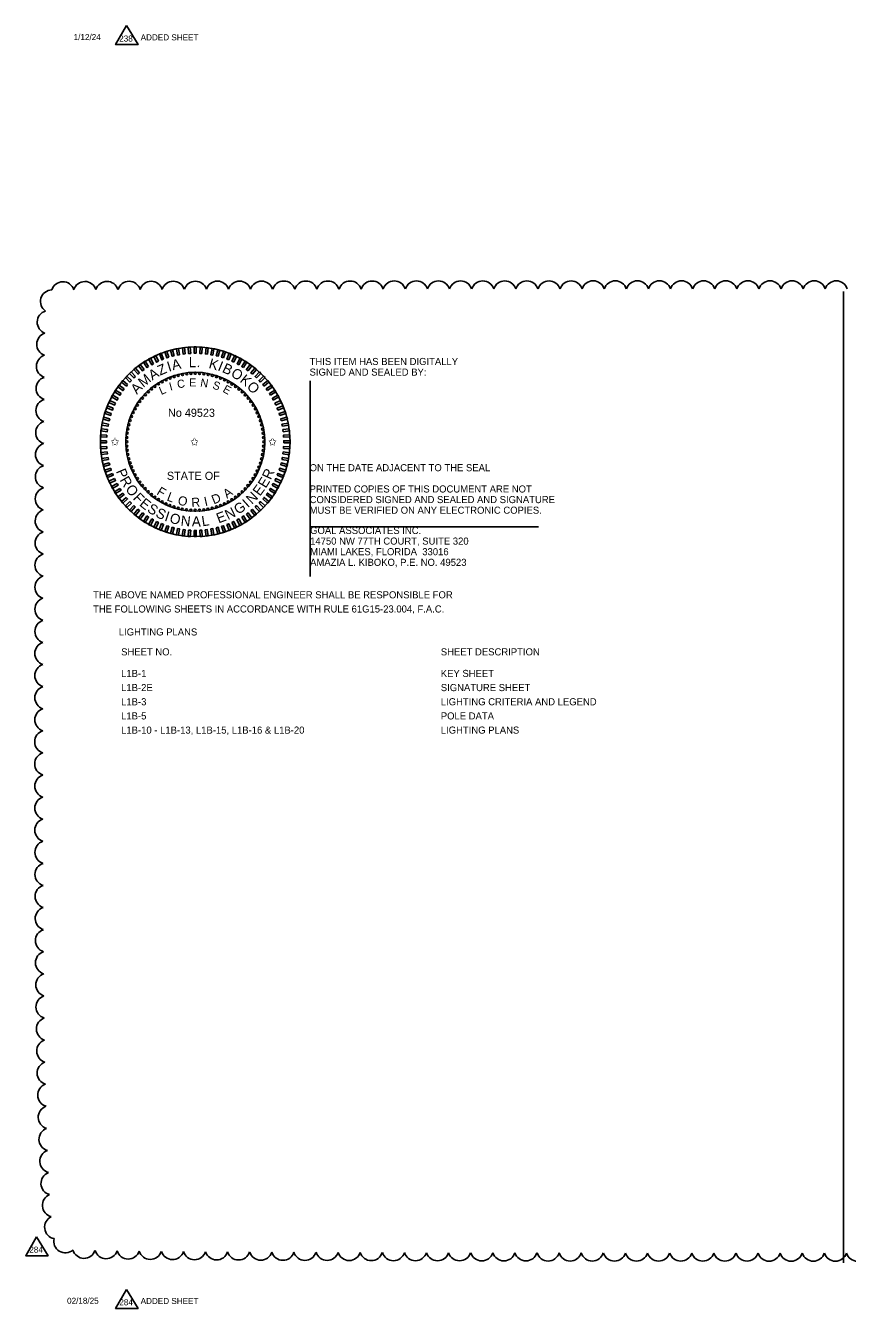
# Model space of a CAD drawing. Extents: x -811.2 to -795, y -2307.6 to -2235.1.
# Drawn here: x -811.17 to -803.05, y -2307.46 to -2294.79 of the extents above; entities that cross this region are included whole.
import ezdxf

# ---------------------------------------------------------------- set-up
doc = ezdxf.new("R2010")
doc.units = 0
for name, color, linetype in [('AdhocPoint_dp', 7, 'Continuous'), ('Cloud_dp', 7, 'Continuous'), ('Logo_dp', 7, 'Continuous'), ('TeleMisc', 7, 'Continuous'), ('TextDetails', 7, 'Continuous'), ('TextMinor', 7, 'Continuous'), ('TextMisc', 7, 'Continuous'), ('TextNotes', 7, 'Continuous')]:
    doc.layers.add(name, color=color, linetype=linetype)

msp = doc.modelspace()

# ---------------------------------------------------------------- linework, layer by layer
at = {"layer": 'AdhocPoint_dp'}
for p, q in [((-808.355, -2298.295), (-808.355, -2300.229)), ((-808.355, -2299.739), (-806.098, -2299.739))]:
    msp.add_line(p, q, dxfattribs=at)
at = {"layer": 'Cloud_dp'}
for points in [[(-810.168, -2294.785), (-810.276, -2294.973), (-810.055, -2294.973)], [(-811.057, -2306.754), (-811.165, -2306.942), (-810.944, -2306.942)], [(-810.168, -2307.274), (-810.276, -2307.462), (-810.055, -2307.462)]]:
    msp.add_lwpolyline(points, close=True, dxfattribs=at)
for centre, start, end in [((-810.798, -2297.43), 18.0566, 163.0566), ((-810.58, -2297.428), 17.7998, 162.7998), ((-810.362, -2297.427), 17.7187, 162.7187), ((-810.143, -2297.426), 17.6743, 162.6743), ((-809.925, -2297.426), 17.6451, 162.6451), ((-809.707, -2297.425), 17.624, 162.624), ((-809.488, -2297.425), 17.6079, 162.6079), ((-809.27, -2297.424), 17.5951, 162.5951), ((-809.052, -2297.424), 17.5845, 162.5845), ((-808.834, -2297.424), 17.5756, 162.5756), ((-808.615, -2297.423), 17.568, 162.568), ((-808.397, -2297.423), 17.5614, 162.5614), ((-808.179, -2297.423), 17.5556, 162.5556), ((-807.96, -2297.423), 17.5505, 162.5505), ((-807.742, -2297.423), 17.5459, 162.5459), ((-807.524, -2297.422), 17.5417, 162.5417), ((-807.305, -2297.422), 17.5379, 162.5379), ((-807.087, -2297.422), 17.5344, 162.5344), ((-806.869, -2297.422), 17.5313, 162.5313), ((-806.65, -2297.422), 17.5283, 162.5283), ((-806.432, -2297.422), 17.5256, 162.5256), ((-806.214, -2297.422), 17.5231, 162.5231), ((-805.995, -2297.422), 17.5207, 162.5207), ((-805.777, -2297.422), 17.5185, 162.5185), ((-805.559, -2297.421), 17.5164, 162.5164), ((-805.34, -2297.421), 17.5145, 162.5145), ((-805.122, -2297.421), 17.5126, 162.5126), ((-804.904, -2297.421), 17.5109, 162.5109), ((-804.685, -2297.421), 17.5092, 162.5092), ((-804.467, -2297.421), 17.5077, 162.5077), ((-804.249, -2297.421), 17.5062, 162.5062), ((-804.03, -2297.421), 17.5048, 162.5048), ((-803.812, -2297.421), 17.5034, 162.5034), ((-803.594, -2297.421), 17.5021, 162.5021), ((-803.375, -2297.421), 17.5009, 162.5009), ((-803.157, -2297.421), 17.5, 162.5), ((-810.905, -2297.511), 91.4771, 236.4771), ((-810.937, -2297.716), 105.908, 250.908), ((-810.942, -2297.934), 106.4168, 251.4168), ((-810.945, -2298.152), 106.6762, 251.6762), ((-810.948, -2298.37), 106.841, 251.841), ((-810.95, -2298.589), 106.9576, 251.9576), ((-810.952, -2298.807), 107.0457, 252.0457), ((-810.954, -2299.025), 107.1154, 252.1154), ((-810.955, -2299.243), 107.1722, 252.1722), ((-810.956, -2299.462), 107.2198, 252.2198), ((-810.957, -2299.68), 107.2603, 252.2603), ((-810.958, -2299.898), 107.2954, 252.2954), ((-810.959, -2300.117), 107.3262, 252.3262), ((-810.96, -2300.335), 107.3535, 252.3535), ((-810.96, -2300.553), 107.3779, 252.3779), ((-810.96, -2300.772), 107.3998, 252.3998), ((-810.961, -2300.99), 107.4198, 252.4198), ((-810.961, -2301.208), 107.438, 252.438), ((-810.961, -2301.427), 107.4547, 252.4547), ((-810.961, -2301.645), 107.4701, 252.4701), ((-810.962, -2301.863), 107.4843, 252.4843), ((-810.962, -2302.081), 107.499, 252.499), ((-810.961, -2302.3), 107.5356, 252.5356), ((-810.961, -2302.518), 107.5822, 252.5822), ((-810.961, -2302.736), 107.6325, 252.6325), ((-810.96, -2302.955), 107.6869, 252.6869), ((-810.959, -2303.173), 107.7461, 252.7461), ((-810.958, -2303.391), 107.8108, 252.8108), ((-810.957, -2303.61), 107.8818, 252.8818), ((-810.955, -2303.828), 107.9604, 252.9604), ((-810.954, -2304.046), 108.0479, 253.0479), ((-810.951, -2304.264), 108.1461, 253.1461), ((-810.949, -2304.483), 108.2576, 253.2576), ((-810.945, -2304.701), 108.3854, 253.3854), ((-810.942, -2304.919), 108.534, 253.534), ((-810.938, -2305.137), 108.7099, 253.7099), ((-810.932, -2305.355), 108.9225, 253.9225), ((-810.927, -2305.573), 109.1867, 254.1867), ((-810.92, -2305.791), 109.5275, 254.5275), ((-810.911, -2306.009), 109.9909, 254.9909), ((-810.9, -2306.227), 110.6749, 255.6749), ((-810.886, -2306.444), 111.8417, 256.8417), ((-810.864, -2306.66), 114.6718, 259.6718), ((-810.774, -2306.799), 166.2299, 311.2299), ((-810.588, -2306.854), 196.1072, 341.1072), ((-810.37, -2306.858), 196.5738, 341.5738), ((-810.152, -2306.861), 196.7877, 341.7877), ((-809.934, -2306.864), 196.9179, 341.9179), ((-809.715, -2306.866), 197.008, 342.008), ((-809.497, -2306.867), 197.075, 342.075), ((-809.279, -2306.869), 197.1274, 342.1274), ((-809.061, -2306.87), 197.1699, 342.1699), ((-808.842, -2306.872), 197.2052, 342.2052), ((-808.624, -2306.873), 197.2352, 342.2352), ((-808.406, -2306.874), 197.261, 342.261), ((-808.187, -2306.874), 197.2836, 342.2836), ((-807.969, -2306.875), 197.3036, 342.3036), ((-807.751, -2306.876), 197.3214, 342.3214), ((-807.532, -2306.877), 197.3374, 342.3374), ((-807.314, -2306.877), 197.3519, 342.3519), ((-807.096, -2306.878), 197.3651, 342.3651), ((-806.878, -2306.878), 197.3773, 342.3773), ((-806.659, -2306.879), 197.3884, 342.3884), ((-806.441, -2306.879), 197.3987, 342.3987), ((-806.223, -2306.879), 197.4083, 342.4083), ((-806.004, -2306.88), 197.4172, 342.4172), ((-805.786, -2306.88), 197.4256, 342.4256), ((-805.568, -2306.88), 197.4334, 342.4334), ((-805.349, -2306.881), 197.4407, 342.4407), ((-805.131, -2306.881), 197.4476, 342.4476), ((-804.913, -2306.881), 197.4542, 342.4542), ((-804.694, -2306.881), 197.4604, 342.4604), ((-804.476, -2306.881), 197.4662, 342.4662), ((-804.258, -2306.881), 197.4718, 342.4718), ((-804.039, -2306.881), 197.4771, 342.4771), ((-803.821, -2306.882), 197.4821, 342.4821), ((-803.603, -2306.882), 197.487, 342.487), ((-803.384, -2306.882), 197.4916, 342.4916), ((-803.166, -2306.882), 197.496, 342.496), ((-802.948, -2306.882), 197.5011, 342.5011)]:
    msp.add_arc(centre, 0.114, start, end, dxfattribs=at)
at = {"layer": 'TextDetails'}
for radius in [0.937, 0.687]:
    msp.add_circle((-809.49, -2298.898), radius, dxfattribs=at)
at = {"layer": 'TextMisc'}
for p, q in [((-809.5, -2299.835), (-809.5, -2299.773)), ((-809.49, -2299.835), (-809.49, -2299.773)), ((-809.48, -2299.835), (-809.48, -2299.773))]:
    msp.add_line(p, q, dxfattribs=at)
for points in [[(-809.698, -2298.048), (-809.717, -2298.053), (-809.733, -2297.993), (-809.713, -2297.988)], [(-809.644, -2298.037), (-809.664, -2298.041), (-809.676, -2297.979), (-809.656, -2297.976)], [(-809.59, -2298.029), (-809.61, -2298.031), (-809.617, -2297.97), (-809.597, -2297.967)], [(-809.535, -2298.024), (-809.555, -2298.026), (-809.559, -2297.963), (-809.539, -2297.962)], [(-809.48, -2298.023), (-809.5, -2298.023), (-809.5, -2297.961), (-809.48, -2297.961)], [(-809.425, -2298.026), (-809.445, -2298.024), (-809.441, -2297.962), (-809.421, -2297.963)], [(-809.37, -2298.031), (-809.39, -2298.029), (-809.383, -2297.967), (-809.363, -2297.97)], [(-809.316, -2298.041), (-809.336, -2298.037), (-809.324, -2297.976), (-809.305, -2297.979)], [(-809.263, -2298.053), (-809.282, -2298.048), (-809.267, -2297.988), (-809.247, -2297.993)], [(-809.95, -2298.154), (-809.967, -2298.165), (-810.001, -2298.112), (-809.984, -2298.101)], [(-809.903, -2298.127), (-809.92, -2298.136), (-809.95, -2298.082), (-809.933, -2298.072)], [(-809.853, -2298.102), (-809.872, -2298.111), (-809.898, -2298.054), (-809.88, -2298.046)], [(-809.803, -2298.081), (-809.821, -2298.088), (-809.844, -2298.03), (-809.826, -2298.023)], [(-809.751, -2298.063), (-809.77, -2298.069), (-809.789, -2298.01), (-809.77, -2298.004)], [(-809.21, -2298.069), (-809.229, -2298.063), (-809.21, -2298.004), (-809.191, -2298.01)], [(-809.159, -2298.088), (-809.177, -2298.081), (-809.154, -2298.023), (-809.136, -2298.03)], [(-809.108, -2298.111), (-809.127, -2298.102), (-809.1, -2298.046), (-809.082, -2298.054)], [(-809.06, -2298.136), (-809.077, -2298.127), (-809.047, -2298.072), (-809.03, -2298.082)], [(-809.013, -2298.165), (-809.03, -2298.154), (-808.996, -2298.101), (-808.979, -2298.112)], [(-810.121, -2298.292), (-810.135, -2298.307), (-810.18, -2298.264), (-810.166, -2298.249)], [(-810.081, -2298.253), (-810.096, -2298.267), (-810.139, -2298.222), (-810.124, -2298.208)], [(-810.04, -2298.218), (-810.055, -2298.23), (-810.095, -2298.182), (-810.08, -2298.169)], [(-809.996, -2298.184), (-810.012, -2298.196), (-810.049, -2298.146), (-810.033, -2298.134)], [(-808.968, -2298.196), (-808.984, -2298.184), (-808.947, -2298.134), (-808.931, -2298.146)], [(-808.925, -2298.231), (-808.94, -2298.218), (-808.9, -2298.17), (-808.885, -2298.182)], [(-808.884, -2298.267), (-808.899, -2298.254), (-808.856, -2298.208), (-808.841, -2298.222)], [(-808.846, -2298.307), (-808.859, -2298.292), (-808.814, -2298.249), (-808.8, -2298.264)], [(-810.192, -2298.376), (-810.204, -2298.392), (-810.254, -2298.355), (-810.242, -2298.339)], [(-810.158, -2298.333), (-810.17, -2298.348), (-810.219, -2298.308), (-810.206, -2298.293)], [(-808.81, -2298.348), (-808.823, -2298.333), (-808.774, -2298.293), (-808.762, -2298.309)], [(-808.777, -2298.392), (-808.788, -2298.376), (-808.738, -2298.339), (-808.726, -2298.355)], [(-810.277, -2298.516), (-810.286, -2298.535), (-810.342, -2298.508), (-810.334, -2298.49)], [(-810.252, -2298.468), (-810.261, -2298.485), (-810.316, -2298.455), (-810.306, -2298.438)], [(-810.223, -2298.421), (-810.234, -2298.438), (-810.287, -2298.404), (-810.276, -2298.387)], [(-808.746, -2298.438), (-808.757, -2298.421), (-808.704, -2298.387), (-808.693, -2298.404)], [(-808.719, -2298.486), (-808.728, -2298.468), (-808.674, -2298.438), (-808.664, -2298.455)], [(-808.694, -2298.535), (-808.703, -2298.517), (-808.646, -2298.49), (-808.638, -2298.508)], [(-810.319, -2298.618), (-810.325, -2298.637), (-810.384, -2298.618), (-810.378, -2298.599)], [(-810.3, -2298.567), (-810.307, -2298.585), (-810.365, -2298.562), (-810.358, -2298.544)], [(-808.673, -2298.585), (-808.681, -2298.567), (-808.623, -2298.544), (-808.615, -2298.562)], [(-808.655, -2298.637), (-808.661, -2298.618), (-808.602, -2298.599), (-808.596, -2298.618)], [(-810.347, -2298.724), (-810.351, -2298.744), (-810.412, -2298.732), (-810.409, -2298.712)], [(-810.335, -2298.671), (-810.34, -2298.69), (-810.4, -2298.675), (-810.395, -2298.655)], [(-808.64, -2298.69), (-808.645, -2298.671), (-808.585, -2298.655), (-808.58, -2298.675)], [(-808.629, -2298.744), (-808.633, -2298.724), (-808.571, -2298.713), (-808.568, -2298.732)], [(-810.362, -2298.833), (-810.364, -2298.853), (-810.426, -2298.849), (-810.425, -2298.829)], [(-810.357, -2298.778), (-810.359, -2298.798), (-810.421, -2298.79), (-810.419, -2298.77)], [(-808.621, -2298.798), (-808.624, -2298.778), (-808.562, -2298.771), (-808.559, -2298.791)], [(-808.617, -2298.853), (-808.618, -2298.833), (-808.556, -2298.829), (-808.554, -2298.849)], [(-810.365, -2298.888), (-810.365, -2298.908), (-810.427, -2298.908), (-810.427, -2298.888)], [(-810.364, -2298.943), (-810.362, -2298.963), (-810.425, -2298.967), (-810.426, -2298.947)], [(-810.359, -2298.998), (-810.357, -2299.018), (-810.419, -2299.025), (-810.421, -2299.005)], [(-808.624, -2299.018), (-808.621, -2298.998), (-808.559, -2299.006), (-808.562, -2299.026)], [(-808.618, -2298.963), (-808.617, -2298.943), (-808.554, -2298.947), (-808.556, -2298.967)], [(-808.615, -2298.908), (-808.615, -2298.888), (-808.553, -2298.888), (-808.553, -2298.908)], [(-810.351, -2299.052), (-810.347, -2299.072), (-810.409, -2299.083), (-810.413, -2299.064)], [(-810.34, -2299.106), (-810.335, -2299.125), (-810.395, -2299.141), (-810.4, -2299.121)], [(-808.645, -2299.125), (-808.64, -2299.106), (-808.58, -2299.121), (-808.585, -2299.141)], [(-808.633, -2299.072), (-808.629, -2299.052), (-808.568, -2299.064), (-808.572, -2299.084)], [(-810.325, -2299.159), (-810.319, -2299.178), (-810.378, -2299.197), (-810.384, -2299.178)], [(-810.307, -2299.211), (-810.3, -2299.229), (-810.358, -2299.252), (-810.365, -2299.233)], [(-810.286, -2299.261), (-810.277, -2299.279), (-810.334, -2299.306), (-810.342, -2299.288)], [(-808.703, -2299.28), (-808.694, -2299.261), (-808.638, -2299.288), (-808.647, -2299.306)], [(-808.681, -2299.229), (-808.673, -2299.211), (-808.615, -2299.234), (-808.623, -2299.252)], [(-808.661, -2299.178), (-808.655, -2299.159), (-808.596, -2299.178), (-808.602, -2299.197)], [(-810.262, -2299.31), (-810.252, -2299.328), (-810.306, -2299.358), (-810.316, -2299.341)], [(-810.234, -2299.358), (-810.223, -2299.375), (-810.276, -2299.409), (-810.287, -2299.392)], [(-808.757, -2299.375), (-808.746, -2299.358), (-808.694, -2299.392), (-808.704, -2299.409)], [(-808.729, -2299.328), (-808.719, -2299.311), (-808.664, -2299.341), (-808.674, -2299.358)], [(-810.204, -2299.404), (-810.192, -2299.42), (-810.242, -2299.457), (-810.254, -2299.441)], [(-810.171, -2299.448), (-810.158, -2299.463), (-810.206, -2299.503), (-810.219, -2299.487)], [(-810.135, -2299.489), (-810.121, -2299.504), (-810.166, -2299.547), (-810.18, -2299.532)], [(-808.859, -2299.504), (-808.846, -2299.489), (-808.8, -2299.532), (-808.814, -2299.547)], [(-808.823, -2299.463), (-808.81, -2299.448), (-808.762, -2299.488), (-808.775, -2299.503)], [(-808.788, -2299.42), (-808.777, -2299.404), (-808.726, -2299.441), (-808.738, -2299.457)], [(-810.096, -2299.529), (-810.082, -2299.542), (-810.124, -2299.588), (-810.139, -2299.574)], [(-810.056, -2299.565), (-810.04, -2299.578), (-810.08, -2299.626), (-810.095, -2299.614)], [(-810.012, -2299.6), (-809.996, -2299.611), (-810.033, -2299.662), (-810.049, -2299.65)], [(-809.967, -2299.631), (-809.95, -2299.642), (-809.984, -2299.695), (-810.001, -2299.684)], [(-809.03, -2299.642), (-809.013, -2299.631), (-808.98, -2299.684), (-808.997, -2299.695)], [(-808.984, -2299.612), (-808.968, -2299.6), (-808.931, -2299.65), (-808.948, -2299.662)], [(-808.94, -2299.578), (-808.925, -2299.566), (-808.885, -2299.614), (-808.901, -2299.627)], [(-808.899, -2299.543), (-808.884, -2299.529), (-808.841, -2299.574), (-808.856, -2299.588)], [(-809.92, -2299.66), (-809.903, -2299.669), (-809.933, -2299.724), (-809.95, -2299.714)], [(-809.872, -2299.685), (-809.853, -2299.694), (-809.88, -2299.75), (-809.898, -2299.742)], [(-809.822, -2299.707), (-809.803, -2299.715), (-809.826, -2299.773), (-809.845, -2299.766)], [(-809.77, -2299.727), (-809.751, -2299.733), (-809.77, -2299.792), (-809.789, -2299.786)], [(-809.718, -2299.743), (-809.698, -2299.748), (-809.713, -2299.808), (-809.733, -2299.803)], [(-809.664, -2299.755), (-809.644, -2299.759), (-809.656, -2299.82), (-809.676, -2299.817)], [(-809.61, -2299.764), (-809.59, -2299.767), (-809.598, -2299.829), (-809.618, -2299.826)], [(-809.555, -2299.77), (-809.535, -2299.772), (-809.539, -2299.834), (-809.559, -2299.833)], [(-809.5, -2299.773), (-809.48, -2299.773), (-809.48, -2299.835), (-809.5, -2299.835)], [(-809.445, -2299.772), (-809.425, -2299.77), (-809.421, -2299.833), (-809.441, -2299.834)], [(-809.391, -2299.767), (-809.371, -2299.765), (-809.363, -2299.826), (-809.383, -2299.829)], [(-809.336, -2299.759), (-809.316, -2299.755), (-809.305, -2299.817), (-809.325, -2299.82)], [(-809.282, -2299.748), (-809.263, -2299.743), (-809.247, -2299.803), (-809.267, -2299.808)], [(-809.23, -2299.733), (-809.21, -2299.727), (-809.191, -2299.786), (-809.21, -2299.792)], [(-809.178, -2299.715), (-809.159, -2299.708), (-809.136, -2299.766), (-809.155, -2299.773)], [(-809.127, -2299.694), (-809.109, -2299.685), (-809.082, -2299.742), (-809.1, -2299.75)], [(-809.078, -2299.669), (-809.06, -2299.66), (-809.03, -2299.714), (-809.048, -2299.724)]]:
    msp.add_lwpolyline(points, close=True, dxfattribs=at)
for centre in [(-809.699, -2298.254), (-809.658, -2298.242), (-809.616, -2298.233), (-809.574, -2298.226), (-809.532, -2298.222), (-809.49, -2298.221), (-809.447, -2298.222), (-809.405, -2298.226), (-809.363, -2298.233), (-809.321, -2298.242), (-809.28, -2298.254), (-809.921, -2298.376), (-809.888, -2298.35), (-809.853, -2298.326), (-809.816, -2298.304), (-809.778, -2298.285), (-809.739, -2298.268), (-809.24, -2298.269), (-809.201, -2298.285), (-809.163, -2298.305), (-809.127, -2298.327), (-809.092, -2298.35), (-809.058, -2298.377), (-810.038, -2298.499), (-810.012, -2298.466), (-809.983, -2298.434), (-809.953, -2298.404), (-809.026, -2298.405), (-808.996, -2298.435), (-808.968, -2298.467), (-808.942, -2298.5), (-810.103, -2298.609), (-810.083, -2298.571), (-810.062, -2298.535), (-808.918, -2298.536), (-808.896, -2298.572), (-808.877, -2298.61), (-810.155, -2298.771), (-810.146, -2298.729), (-810.134, -2298.688), (-810.12, -2298.648), (-808.86, -2298.649), (-808.846, -2298.689), (-808.834, -2298.73), (-810.167, -2298.897), (-810.166, -2298.855), (-810.162, -2298.813), (-808.825, -2298.772), (-808.818, -2298.814), (-808.814, -2298.856), (-810.166, -2298.94), (-810.162, -2298.982), (-810.155, -2299.024), (-808.818, -2298.983), (-808.814, -2298.941), (-808.813, -2298.899), (-810.146, -2299.066), (-810.134, -2299.107), (-810.12, -2299.147), (-808.861, -2299.148), (-808.846, -2299.108), (-808.834, -2299.067), (-808.825, -2299.025), (-810.103, -2299.186), (-810.084, -2299.224), (-810.062, -2299.26), (-808.919, -2299.261), (-808.897, -2299.225), (-808.878, -2299.187), (-810.038, -2299.296), (-810.012, -2299.329), (-809.984, -2299.361), (-809.954, -2299.391), (-809.027, -2299.392), (-808.997, -2299.362), (-808.969, -2299.33), (-808.943, -2299.296), (-809.922, -2299.419), (-809.889, -2299.446), (-809.853, -2299.469), (-809.817, -2299.491), (-809.779, -2299.51), (-809.74, -2299.527), (-809.241, -2299.528), (-809.202, -2299.511), (-809.164, -2299.492), (-809.128, -2299.47), (-809.093, -2299.446), (-809.059, -2299.42), (-809.7, -2299.542), (-809.659, -2299.554), (-809.618, -2299.563), (-809.576, -2299.57), (-809.533, -2299.574), (-809.49, -2299.575), (-809.448, -2299.574), (-809.406, -2299.57), (-809.364, -2299.563), (-809.322, -2299.554), (-809.281, -2299.542)]:
    msp.add_circle(centre, 0.01, dxfattribs=at)
at = {"layer": 'TextNotes'}
msp.add_line((-803.086, -2307.012), (-803.086, -2297.412), dxfattribs=at)

# ---------------------------------------------------------------- texts
at = {"layer": 'Cloud_dp'}
for s, p in [('238', (-810.241, -2294.943)), ('284', (-811.129, -2306.912)), ('284', (-810.24, -2307.432))]:
    msp.add_text(s, height=0.06, rotation=0, dxfattribs=at).set_placement(p)
at = {"layer": 'Logo_dp'}
for s, height, rotation, p in [('Z', 0.1, 23.3052, (-809.837, -2298.245)), ('I', 0.1, 17.6836, (-809.75, -2298.207)), ('A', 0.1, 11.9184, (-809.711, -2298.191)), ('L', 0.1, 359.9662, (-809.554, -2298.161)), ('K', 0.1, 344.2727, (-809.363, -2298.168)), ('I', 0.1, 337.7777, (-809.275, -2298.19)), ('B', 0.1, 334.487, (-809.231, -2298.205)), ('M', 0.1, 39.3, (-810.003, -2298.366)), ('A', 0.1, 31.466, (-809.914, -2298.294)), ('.', 0.1, 353.7858, (-809.477, -2298.158)), ('O', 0.1, 327.8239, (-809.146, -2298.244)), ('K', 0.1, 321.0594, (-809.056, -2298.301)), ('A', 0.1, 46.8094, (-810.066, -2298.434)), ('O', 0.1, 314.2033, (-808.987, -2298.359)), ('P', 0.1, 293.1955, (-810.275, -2299.189)), ('R', 0.1, 300.2595, (-810.239, -2299.275)), ('E', 0.1, 58.6169, (-808.793, -2299.363)), ('R', 0.1, 65.2886, (-808.744, -2299.279)), ('O', 0.1, 307.2662, (-810.185, -2299.367)), ('F', 0.09, 328.534, (-809.878, -2299.413)), ('A', 0.09, 35.5463, (-809.176, -2299.462)), ('N', 0.1, 44.3421, (-808.93, -2299.521)), ('E', 0.1, 53.9986, (-808.85, -2299.441)), ('F', 0.1, 314.2033, (-810.111, -2299.46)), ('E', 0.1, 321.0594, (-810.048, -2299.523)), ('S', 0.1, 327.8239, (-809.972, -2299.584)), ('L', 0.09, 339.4875, (-809.777, -2299.476)), ('O', 0.09, 348.0816, (-809.668, -2299.517)), ('R', 0.09, 3.1074, (-809.526, -2299.543)), ('I', 0.09, 12.5248, (-809.392, -2299.534)), ('D', 0.09, 22.2223, (-809.307, -2299.517)), ('G', 0.1, 34.1136, (-809.066, -2299.621)), ('I', 0.1, 41.8391, (-808.97, -2299.555)), ('S', 0.1, 334.487, (-809.889, -2299.635)), ('I', 0.1, 341.04, (-809.8, -2299.676)), ('O', 0.1, 344.2727, (-809.751, -2299.694)), ('N', 0.1, 353.7858, (-809.637, -2299.724)), ('A', 0.1, 359.9662, (-809.524, -2299.735)), ('L', 0.1, 8.9826, (-809.419, -2299.734)), ('E', 0.1, 20.5125, (-809.259, -2299.705)), ('N', 0.1, 26.0618, (-809.167, -2299.672))]:
    msp.add_text(s, height=height, rotation=rotation, dxfattribs=at).set_placement(p)
for s, height, p in [('THIS ITEM HAS BEEN DIGITALLY', 0.07, (-808.36, -2298.139)), ('SIGNED AND SEALED BY:', 0.07, (-808.36, -2298.244)), ('No 49523', 0.08, (-809.759, -2298.651)), ('ON THE DATE ADJACENT TO THE SEAL', 0.07, (-808.36, -2299.189)), ('STATE OF', 0.08, (-809.77, -2299.274)), ('PRINTED COPIES OF THIS DOCUMENT ARE NOT ', 0.07, (-808.36, -2299.399)), ('CONSIDERED SIGNED AND SEALED AND SIGNATURE ', 0.07, (-808.36, -2299.504)), ('MUST BE VERIFIED ON ANY ELECTRONIC COPIES.', 0.07, (-808.36, -2299.609)), ('GOAL ASSOCIATES INC.', 0.07, (-808.355, -2299.809)), ('14750 NW 77TH COURT, SUITE 320', 0.07, (-808.355, -2299.914)), ('MIAMI LAKES, FLORIDA  33016', 0.07, (-808.355, -2300.019)), ('AMAZIA L. KIBOKO, P.E. NO. 49523', 0.07, (-808.355, -2300.124)), ('THE ABOVE NAMED PROFESSIONAL ENGINEER SHALL BE RESPONSIBLE FOR ', 0.07, (-810.499, -2300.445)), ('THE FOLLOWING SHEETS IN ACCORDANCE WITH RULE 61G15-23.004, F.A.C.', 0.07, (-810.499, -2300.585)), ('LIGHTING PLANS', 0.07, (-810.245, -2300.812))]:
    msp.add_text(s, height=height, dxfattribs=at).set_placement(p)
at = {"layer": 'TeleMisc'}
for s, p in [('SHEET NO.', (-810.222, -2301.009)), ('SHEET DESCRIPTION', (-807.064, -2301.009)), ('L1B-1', (-810.222, -2301.222)), ('KEY SHEET', (-807.064, -2301.222)), ('L1B-2E', (-810.222, -2301.362)), ('SIGNATURE SHEET', (-807.064, -2301.362)), ('L1B-3', (-810.222, -2301.502)), ('LIGHTING CRITERIA AND LEGEND', (-807.064, -2301.502)), ('L1B-5', (-810.222, -2301.642)), ('POLE DATA', (-807.064, -2301.642)), ('L1B-10 - L1B-13, L1B-15, L1B-16 & L1B-20', (-810.222, -2301.782)), ('LIGHTING PLANS', (-807.064, -2301.782))]:
    msp.add_text(s, height=0.07, dxfattribs=at).set_placement(p)
at = {"layer": 'TextMinor'}
for s, p in [('1/12/24', (-810.691, -2294.928)), ('ADDED SHEET', (-810.029, -2294.931)), ('02/18/25', (-810.756, -2307.417)), ('ADDED SHEET', (-810.029, -2307.419))]:
    msp.add_text(s, height=0.06, dxfattribs=at).set_placement(p)
at = {"layer": 'TextMisc'}
for s, rotation, p in [('L', 23.3052, (-809.826, -2298.436)), ('I', 14.8189, (-809.736, -2298.393)), ('C', 8.9826, (-809.663, -2298.37)), ('E', 359.9662, (-809.55, -2298.351)), ('N', 350.6464, (-809.444, -2298.35)), ('S', 341.04, (-809.326, -2298.369)), ('E', 331.1686, (-809.225, -2298.401))]:
    msp.add_text(s, height=0.08, rotation=rotation, dxfattribs=at).set_placement(p)
for p in [(-810.325, -2298.936), (-809.54, -2298.936), (-808.769, -2298.936)]:
    msp.add_text('✩', height=0.08, dxfattribs=at).set_placement(p)

doc.saveas('drawing.dxf')
